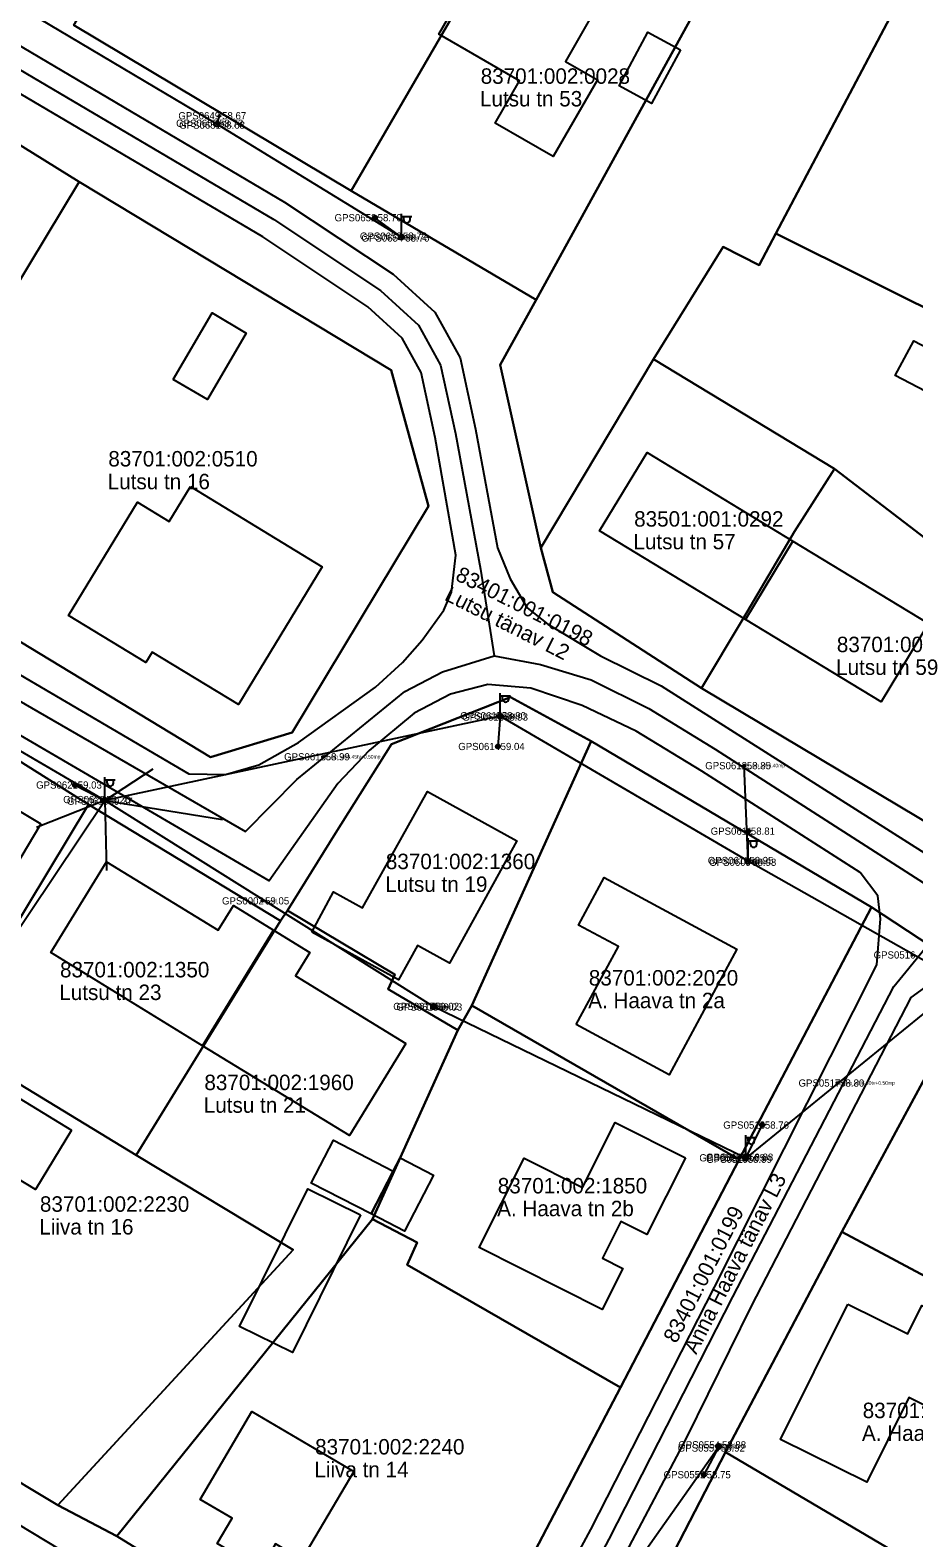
# Model space of a CAD drawing. Extents: x 580119 to 583377, y 6518915 to 6520820.
# Drawn here: x 581860.5 to 581946.3, y 6520226.6 to 6520373 of the extents above; entities that cross this region are included whole.
import ezdxf

# ---------------------------------------------------------------- set-up
doc = ezdxf.new("R2010")
doc.units = 0
for name, color, linetype in [('Hoone Elu- või ühiskondlik hoone', 7, 'Continuous'), ('Hoone Kõrval- või tootmishoone', 7, 'Continuous'), ('Hoone Vundament', 7, 'Continuous'), ('L_AADRESS', 7, 'Continuous'), ('MAAMUDEL', 7, 'Continuous'), ('MOOTKORG-EH2000', 7, 'Continuous'), ('MOOTMPUNKT', 7, 'Continuous'), ('MOOTNR', 7, 'Continuous'), ('MPOHULIIN', 7, 'Continuous'), ('PIIR', 7, 'Continuous'), ('POST', 7, 'Continuous'), ('Rippe kõrgus', 7, 'Continuous'), ('SIOHULIIN', 7, 'Continuous'), ('Tee Liiklusala', 7, 'Continuous'), ('Tee Tänav Püsikate', 7, 'Continuous'), ('TUNNUS', 7, 'Continuous')]:
    doc.layers.add(name, color=color, linetype=linetype)

msp = doc.modelspace()

# ---------------------------------------------------------------- linework, layer by layer
at = {"layer": 'Hoone Elu- või ühiskondlik hoone'}
for points in [[(581915.6, 6520368.18), (581911.32, 6520360.75), (581905.69, 6520363.98), (581908.05, 6520368.09), (581900.19, 6520372.62), (581905.37, 6520381.61), (581915.75, 6520375.63), (581912.49, 6520369.96)], [(581934.59, 6520323.38), (581929.97, 6520315.78), (581915.8, 6520324.38), (581920.42, 6520331.99)], [(581876.09, 6520328.69), (581888.89, 6520320.91), (581880.76, 6520307.52), (581872.37, 6520312.61), (581871.75, 6520311.61), (581864.25, 6520316.17), (581870.94, 6520327.17), (581874.03, 6520325.3)], [(581947.76, 6520315.39), (581943.15, 6520307.8), (581929.97, 6520315.78), (581934.59, 6520323.38)], [(581861.56, 6520295.95), (581856.33, 6520287.17), (581843.89, 6520294.57), (581845.86, 6520297.89), (581843.52, 6520299.28), (581848.15, 6520307.06), (581851.89, 6520304.84), (581850.52, 6520302.53)], [(581887.87, 6520285.43), (581889.97, 6520289.33), (581892.8, 6520287.77), (581899.11, 6520299.09), (581907.79, 6520294.29), (581901.23, 6520282.4), (581898.12, 6520284.11), (581896.29, 6520280.79)], [(581867.93, 6520292.26), (581878.78, 6520285.61), (581880.26, 6520288), (581884.15, 6520285.62), (581877.27, 6520274.39), (581862.52, 6520283.43)], [(581897.01, 6520274.62), (581891.52, 6520265.66), (581877.27, 6520274.39), (581884.15, 6520285.62), (581887.67, 6520283.46), (581886.28, 6520281.18)], [(581924.16, 6520263.52), (581920.4, 6520256.05), (581917.89, 6520257.31), (581916.1, 6520253.75), (581918.07, 6520252.76), (581916.07, 6520248.79), (581904.13, 6520254.79), (581908.49, 6520263.47), (581914.15, 6520260.63), (581917.33, 6520266.95)], [(581939.93, 6520249.3), (581945.73, 6520246.42), (581947.11, 6520249.18), (581953.35, 6520246.07), (581949.53, 6520238.4), (581945.84, 6520240.22), (581941.75, 6520232), (581933.39, 6520236.16)], [(581891.94, 6520233.04), (581886.91, 6520224.51), (581884.36, 6520226.01), (581882.91, 6520223.56), (581878.68, 6520226.06), (581880.13, 6520228.52), (581877.03, 6520230.34), (581882.05, 6520238.87)]]:
    msp.add_lwpolyline(points, close=True, dxfattribs=at)
at = {"layer": 'Hoone Kõrval- või tootmishoone'}
for points in [[(581923.66, 6520371.1), (581920.87, 6520365.9), (581917.71, 6520367.6), (581920.5, 6520372.8)], [(581874.4, 6520339.1), (581878.18, 6520345.55), (581881.51, 6520343.6), (581877.73, 6520337.15)], [(581952.19, 6520339.77), (581950.4, 6520336.39), (581944.53, 6520339.46), (581946.33, 6520342.85)], [(581864.55, 6520266.2), (581861.03, 6520260.42), (581855, 6520264.09), (581851.33, 6520258.06), (581844.97, 6520261.93), (581852.17, 6520273.74)], [(581895.77, 6520262.21), (581893.62, 6520258.06), (581887.81, 6520261.06), (581889.96, 6520265.21)], [(581893.62, 6520258.06), (581895.77, 6520262.21), (581896.44, 6520263.5), (581899.68, 6520261.83), (581896.87, 6520256.38)], [(581892.6, 6520257.96), (581885.98, 6520244.59), (581880.84, 6520247.12), (581887.47, 6520260.5)]]:
    msp.add_lwpolyline(points, close=True, dxfattribs=at)
at = {"layer": 'Hoone Vundament'}
msp.add_lwpolyline([(581913.55, 6520276.44), (581917.65, 6520284.03), (581913.78, 6520286.11), (581916.25, 6520290.72), (581929.14, 6520283.76), (581922.56, 6520271.57)], close=True, dxfattribs=at)
at = {"layer": 'MOOTMPUNKT'}
for centre in [(581878.9, 6520364.7), (581878.61, 6520363.97), (581878.77, 6520363.79), (581894, 6520354.8), (581896.46, 6520353.01), (581896.68, 6520352.83), (581906.06, 6520306.44), (581906.26, 6520306.32), (581905.94, 6520303.45), (581888.96, 6520302.45), (581929.85, 6520301.59), (581864.88, 6520299.71), (581867.65, 6520298.3), (581867.88, 6520298.14), (581930.24, 6520295.23), (581930.09, 6520292.38), (581930.37, 6520292.21), (581883.07, 6520288.46), (581946.2, 6520283.21), (581899.56, 6520278.21), (581899.87, 6520278.15), (581938.91, 6520270.77), (581931.6, 6520266.69), (581929.28, 6520263.51), (581930.07, 6520263.57), (581929.95, 6520263.37), (581927.44, 6520235.64), (581927.32, 6520235.33), (581925.95, 6520232.74)]:
    msp.add_circle(centre, 0.1, dxfattribs=at)
at = {"layer": 'MPOHULIIN'}
for p, q in [((581878.69, 6520363.88), (581878.9, 6520364.7)), ((581930.23, 6520292.3), (581929.85, 6520301.59)), ((581899.05, 6520195.29), (581927.38, 6520235.48))]:
    msp.add_line(p, q, dxfattribs=at)
for points in [[(581789.29, 6520345.21), (581806.35, 6520371.05), (581823.38, 6520396.51), (581838.05, 6520387.92), (581858.29, 6520376.01), (581878.69, 6520363.88), (581896.57, 6520352.92)], [(581867.76, 6520298.22), (581843.02, 6520312.69), (581821.56, 6520325.5), (581789.29, 6520345.21), (581785.52, 6520344.9)], [(581951.03, 6520280.57), (581930.23, 6520292.3), (581906.16, 6520306.38), (581867.76, 6520298.22)], [(581841.65, 6520259.23), (581850.68, 6520272.73), (581867.76, 6520298.22)], [(581951.03, 6520280.57), (581930.01, 6520263.47), (581928.35, 6520263.55)], [(581930.01, 6520263.47), (581899.71, 6520278.18)]]:
    msp.add_lwpolyline(points, dxfattribs=at)
at = {"layer": 'PIIR'}
for points in [[(581930.32, 6520416.52), (581957.49, 6520399.79), (581932.94, 6520353.26), (581931.31, 6520350.19), (581927.81, 6520351.97), (581921.06, 6520341.05), (581910.1, 6520322.74), (581906.17, 6520340.51), (581909.67, 6520346.83), (581927.24, 6520378.81), (581913.4, 6520387.09)], [(581883.02, 6520404.8), (581910, 6520388.99), (581891.69, 6520357.4), (581864.77, 6520373.51)], [(581957.49, 6520399.79), (581993.27, 6520378.24), (581969.51, 6520335.03), (581932.94, 6520353.26)], [(581910, 6520388.99), (581913.4, 6520387.09), (581927.24, 6520378.81), (581909.67, 6520346.83), (581891.69, 6520357.4)], [(581798.19, 6520351.98), (581821.38, 6520336.91), (581844, 6520323.04), (581878.03, 6520302.4), (581885.96, 6520304.82), (581899.19, 6520326.8), (581895.57, 6520340), (581865.29, 6520358.29), (581840.03, 6520373.94), (581817.44, 6520386.49)], [(581832.75, 6520354.9), (581829.56, 6520356.9), (581840.03, 6520373.94), (581865.29, 6520358.29), (581844, 6520323.04), (581821.38, 6520336.91)], [(581865.29, 6520358.29), (581895.57, 6520340), (581899.19, 6520326.8), (581885.96, 6520304.82), (581878.03, 6520302.4), (581844, 6520323.04)], [(581921.06, 6520341.05), (581927.81, 6520351.97), (581931.31, 6520350.19), (581932.94, 6520353.26), (581969.51, 6520335.03), (581969.36, 6520330.69), (581961, 6520313.29), (581938.63, 6520330.42)], [(581911.28, 6520318.44), (581910.1, 6520322.74), (581921.06, 6520341.05), (581938.63, 6520330.42), (581934.75, 6520324.34), (581929.71, 6520315.83), (581925.71, 6520309.1)], [(581938.63, 6520330.42), (581961, 6520313.29), (581950.66, 6520294.21), (581925.71, 6520309.1), (581929.71, 6520315.83), (581934.75, 6520324.34)], [(581849.2, 6520308.51), (581866.2, 6520297.82), (581852.4, 6520274.95), (581835.18, 6520285.22)], [(581895.94, 6520281.31), (581885.52, 6520287.54), (581890.17, 6520295.02), (581895.61, 6520303.69), (581907.15, 6520308.24), (581915, 6520303.97), (581903.41, 6520278.31), (581902.06, 6520275.9), (581895.28, 6520279.9)], [(581915, 6520303.97), (581942.22, 6520287.85), (581929.38, 6520263.33), (581903.41, 6520278.31)], [(581866.2, 6520297.82), (581884.83, 6520286.51), (581870.83, 6520263.78), (581852.4, 6520274.95)], [(581884.83, 6520286.51), (581885.52, 6520287.54), (581895.94, 6520281.31), (581895.28, 6520279.9), (581902.06, 6520275.9), (581893.75, 6520257.55), (581868.94, 6520226.76), (581863.22, 6520229.79), (581886.05, 6520254.56), (581870.83, 6520263.78)], [(581910.68, 6520201.36), (581900.21, 6520207.51), (581917.83, 6520241.2), (581929.38, 6520263.33), (581942.22, 6520287.85), (581953.73, 6520280.26), (581951.99, 6520279.75), (581939.33, 6520256.33), (581928.04, 6520234.91)], [(581951.99, 6520279.75), (581953.73, 6520280.26), (581978.64, 6520265.66), (581965.72, 6520242.24), (581939.33, 6520256.33)], [(581898.1, 6520255.28), (581893.75, 6520257.55), (581902.06, 6520275.9), (581903.41, 6520278.31), (581929.38, 6520263.33), (581917.83, 6520241.2), (581897.13, 6520253.13)], [(581841.97, 6520255.88), (581852.4, 6520274.95), (581870.83, 6520263.78), (581886.05, 6520254.56), (581863.22, 6520229.79), (581836.91, 6520245.57)], [(581893.75, 6520257.55), (581898.1, 6520255.28), (581897.13, 6520253.13), (581917.83, 6520241.2), (581900.21, 6520207.51), (581868.94, 6520226.76)], [(581939.33, 6520256.33), (581965.72, 6520242.24), (581963.58, 6520238.14), (581954.1, 6520219.54), (581928.04, 6520234.91)], [(581928.04, 6520234.91), (581954.1, 6520219.54), (581960.82, 6520215.52), (581942.75, 6520182.07), (581910.68, 6520201.36)]]:
    msp.add_lwpolyline(points, close=True, dxfattribs=at)
for points in [[(581953.73, 6520280.26), (581942.22, 6520287.85), (581915, 6520303.97), (581907.15, 6520308.24), (581895.61, 6520303.69), (581890.17, 6520295.02), (581885.52, 6520287.54), (581884.83, 6520286.51), (581866.2, 6520297.82), (581849.2, 6520308.51), (581832.08, 6520318.73), (581821.48, 6520324.8), (581804.32, 6520335.14), (581786.62, 6520345.32), (581785.35, 6520349.14), (581801.36, 6520378.94)], [(581864.77, 6520373.51), (581891.69, 6520357.4), (581909.67, 6520346.83), (581906.17, 6520340.51), (581910.1, 6520322.74), (581911.28, 6520318.44), (581925.71, 6520309.1), (581950.66, 6520294.21)], [(581641.44, 6520358.2), (581663.75, 6520346.68), (581696.78, 6520330.58), (581710.47, 6520322.41), (581741.73, 6520303.41), (581773.45, 6520284.3), (581791.76, 6520272.95), (581801.15, 6520267.32), (581804.72, 6520265.17), (581827.76, 6520250.96), (581836.91, 6520245.57), (581863.22, 6520229.79), (581868.94, 6520226.76), (581900.21, 6520207.51)]]:
    msp.add_lwpolyline(points, dxfattribs=at)
at = {"layer": 'POST'}
for p, q in [((581896.57, 6520353.17), (581896.57, 6520355.17)), ((581896.57, 6520354.92), (581897.57, 6520354.92)), ((581896.8, 6520354.6), (581896.8, 6520354.92)), ((581897.41, 6520354.6), (581897.41, 6520354.92)), ((581896.57, 6520352.92), (581896.57, 6520352.92)), ((581906.16, 6520306.63), (581906.16, 6520308.63)), ((581906.16, 6520308.38), (581907.16, 6520308.38)), ((581906.39, 6520308.06), (581906.39, 6520308.38)), ((581907, 6520308.06), (581907, 6520308.38)), ((581906.16, 6520306.38), (581906.16, 6520306.38)), ((581867.76, 6520298.47), (581867.76, 6520300.47)), ((581867.76, 6520300.22), (581868.76, 6520300.22)), ((581867.99, 6520299.9), (581867.99, 6520300.22)), ((581868.6, 6520299.9), (581868.6, 6520300.22)), ((581867.76, 6520298.22), (581867.76, 6520298.22)), ((581930.23, 6520292.55), (581930.23, 6520294.55)), ((581930.23, 6520294.3), (581931.23, 6520294.3)), ((581930.46, 6520293.97), (581930.46, 6520294.3)), ((581931.07, 6520293.97), (581931.07, 6520294.3)), ((581930.23, 6520292.3), (581930.23, 6520292.3)), ((581930.01, 6520263.72), (581930.01, 6520265.72)), ((581930.01, 6520265.47), (581931.01, 6520265.47)), ((581930.23, 6520265.15), (581930.23, 6520265.47)), ((581930.84, 6520265.15), (581930.84, 6520265.47)), ((581930.01, 6520263.47), (581930.01, 6520263.47))]:
    msp.add_line(p, q, dxfattribs=at)
for points in [[(581896.57, 6520352.92), (581894, 6520354.8)], [(581906.16, 6520306.38), (581905.94, 6520303.45)], [(581864.88, 6520299.71), (581867.76, 6520298.22)], [(581930.01, 6520263.47), (581931.6, 6520266.69)], [(581927.38, 6520235.48), (581925.95, 6520232.74)]]:
    msp.add_lwpolyline(points, dxfattribs=at)
for centre, radius in [((581878.69, 6520363.88), 0.25), ((581894, 6520354.8), 0.2), ((581896.57, 6520352.92), 0.25), ((581906.16, 6520306.38), 0.25), ((581905.94, 6520303.45), 0.2), ((581864.88, 6520299.71), 0.2), ((581867.76, 6520298.22), 0.25), ((581930.24, 6520295.23), 0.2), ((581930.23, 6520292.3), 0.25), ((581899.71, 6520278.18), 0.25), ((581899.71, 6520278.18), 0.0234), ((581931.6, 6520266.69), 0.2), ((581930.01, 6520263.47), 0.25), ((581927.38, 6520235.48), 0.25), ((581925.95, 6520232.74), 0.2)]:
    msp.add_circle(centre, radius, dxfattribs=at)
for centre in [(581897.1, 6520354.6), (581906.69, 6520308.06), (581868.3, 6520299.9), (581930.77, 6520293.97), (581930.54, 6520265.15)]:
    msp.add_arc(centre, 0.306, 180, 0, dxfattribs=at)
at = {"layer": 'SIOHULIIN'}
for q in [(581872.48, 6520301.27), (581861.13, 6520295.58), (581867.95, 6520291.41)]:
    msp.add_line((581867.76, 6520298.22), q, dxfattribs=at)
for points in [[(581867.76, 6520298.22), (581879.19, 6520296.36)], [(581899.71, 6520278.18), (581867.76, 6520298.22)]]:
    msp.add_lwpolyline(points, dxfattribs=at)
at = {"layer": 'Tee Liiklusala'}
for points in [[(581843.85, 6520381.18), (581859.87, 6520371.29), (581885.23, 6520356.32), (581895.77, 6520349.31), (581899.82, 6520345.62), (581902.26, 6520341.18), (581903.77, 6520334.25), (581905.9, 6520322.74), (581907.13, 6520319.74), (581908.78, 6520316.91), (581910.79, 6520315.32), (581915.9, 6520312.25), (581921.78, 6520309.33), (581947.38, 6520293.09)], [(581845.58, 6520318.61), (581875.93, 6520300.79), (581879.5, 6520300.73), (581882.72, 6520301.66), (581886.58, 6520303.83), (581894.07, 6520309.22), (581896.69, 6520311.61), (581898.59, 6520313.79), (581900.69, 6520316.7), (581901.45, 6520318.45), (581901.87, 6520322.02), (581899.85, 6520333.46), (581898.48, 6520339.76), (581896.64, 6520343.11), (581893.3, 6520346.15), (581883.11, 6520352.93), (581857.8, 6520367.86)], [(581905.87, 6520210.56), (581914.97, 6520227.4), (581926.96, 6520250.94), (581942.73, 6520282.24), (581943.1, 6520286.73), (581942.84, 6520288.94), (581941.11, 6520291.22), (581925.73, 6520301.07), (581919.37, 6520304.95), (581914.13, 6520307.42), (581909.15, 6520309.1), (581904.96, 6520309.47), (581901.34, 6520308.53), (581897.81, 6520306.68), (581893.45, 6520303.06), (581890.4, 6520299.87), (581883.73, 6520290.39), (581831.98, 6520320.65)], [(581948.5, 6520280.84), (581946.04, 6520279.06), (581930.52, 6520249.11), (581924.23, 6520236.3), (581909.68, 6520208.73), (581908.39, 6520205.89), (581907.88, 6520203.6), (581907.85, 6520201.97), (581908.78, 6520199.57), (581909.94, 6520197.81), (581951.81, 6520172.47)], [(581822.23, 6520250.37), (581872.96, 6520219.7)]]:
    msp.add_lwpolyline(points, dxfattribs=at)
at = {"layer": 'Tee Tänav Püsikate'}
for points in [[(581829.4, 6520325.26), (581818.11, 6520332.41), (581802.94, 6520342.03), (581797.05, 6520345.98), (581794.58, 6520349.99), (581793.88, 6520354.52), (581794.87, 6520358.14), (581805.2, 6520378.63), (581809.48, 6520385.25), (581812.61, 6520388.5), (581816.17, 6520390.21), (581820.37, 6520391.25), (581824.11, 6520390.41), (581827.72, 6520388.92), (581832.69, 6520386.31), (581842.76, 6520379.5), (581858.83, 6520369.58), (581884.17, 6520354.62), (581894.53, 6520347.73), (581898.23, 6520344.36), (581900.37, 6520340.47), (581901.81, 6520333.85), (581904.24, 6520320.68), (581905.59, 6520312.25)], [(581829.4, 6520325.26), (581847.74, 6520314.64), (581881.43, 6520295.18), (581886.42, 6520300.23), (581896.89, 6520308.78), (581900.56, 6520310.7), (581905.59, 6520312.25)], [(581905.59, 6520312.25), (581910.07, 6520311.41), (581914.98, 6520309.92), (581920.58, 6520307.14), (581927.05, 6520303.19), (581949.43, 6520288.83), (581950.77, 6520287.95)], [(581904.38, 6520197.95), (581905.85, 6520205.86), (581916.75, 6520226.48), (581928.74, 6520250.02), (581944.37, 6520280.16), (581950.77, 6520287.95)]]:
    msp.add_lwpolyline(points, dxfattribs=at)

# ---------------------------------------------------------------- texts
at = {"layer": 'L_AADRESS'}
for s, p in [('Lutsu tn 53', (581904.2, 6520365.6)), ('Lutsu tn 16', (581868.05, 6520328.43)), ('Lutsu tn 57', (581919.1, 6520322.6)), ('Lutsu tn 59', (581938.78, 6520310.4)), ('Lutsu tn 19', (581895, 6520289.33)), ('Lutsu tn 23', (581863.35, 6520278.83)), ('A. Haava tn 2a', (581914.71, 6520278.04)), ('Lutsu tn 21', (581877.38, 6520267.88)), ('A. Haava tn 2b', (581905.87, 6520257.84)), ('Liiva tn 16', (581861.41, 6520256.06)), ('A. Haava tn 3', (581941.29, 6520236.02)), ('Liiva tn 14', (581888.12, 6520232.49))]:
    msp.add_text(s, height=1.5, dxfattribs=at).set_placement(p)
for s, rotation, p in [('Lutsu tänav L2', 333.1829, (581900.65, 6520317.72)), ('Anna Haava tänav L3', 62.8457, (581925.19, 6520244.34))]:
    msp.add_text(s, height=1.5, rotation=rotation, dxfattribs=at).set_placement(p)
at = {"layer": 'MAAMUDEL'}
for s, p in [(' kaabel', (581896.46, 6520352.84)), (' kaabel', (581896.68, 6520352.66)), (' kaabel', (581906.06, 6520306.26)), (' kaabel', (581906.26, 6520306.14)), (' kilp', (581930.09, 6520292.21)), (' kaabel', (581930.09, 6520292.21)), (' kilp', (581930.37, 6520292.03)), (' kaabel', (581930.37, 6520292.03)), (' si_ohl', (581883.07, 6520288.29)), (' kaabel', (581899.56, 6520278.04)), (' kaabel', (581899.87, 6520277.98)), (' kaabel', (581927.44, 6520235.46)), (' kaabel', (581927.32, 6520235.15))]:
    msp.add_text(s, height=0.35, dxfattribs=at).set_placement(p)
at = {"layer": 'MOOTKORG-EH2000'}
for s, p in [(' 58.67', (581878.9, 6520364.35)), (' 58.73', (581878.61, 6520363.62)), (' 58.68', (581878.77, 6520363.44)), (' 58.70', (581894, 6520354.45)), (' 58.72', (581896.46, 6520352.66)), (' 58.76', (581896.68, 6520352.48)), (' 58.90', (581906.06, 6520306.09)), (' 58.93', (581906.26, 6520305.96)), (' 59.04', (581905.94, 6520303.1)), (' 58.99', (581888.96, 6520302.1)), (' 58.85', (581929.85, 6520301.24)), (' 59.03', (581864.88, 6520299.36)), (' 59.20', (581867.65, 6520297.95)), (' 59.37', (581867.88, 6520297.79)), (' 58.81', (581930.24, 6520294.88)), (' 58.95', (581930.09, 6520292.03)), (' 58.93', (581930.37, 6520291.86)), (' 59.05', (581883.07, 6520288.11)), (' 59.02', (581899.56, 6520277.86)), (' 59.03', (581899.87, 6520277.8)), (' 58.80', (581938.91, 6520270.42)), (' 58.76', (581931.6, 6520266.34)), (' 59.05', (581929.28, 6520263.16)), (' 58.99', (581929.95, 6520263.02)), (' 58.88', (581930.07, 6520263.22)), (' 58.92', (581927.32, 6520234.98)), (' 58.88', (581927.44, 6520235.29)), (' 58.75', (581925.95, 6520232.39))]:
    msp.add_text(s, height=0.7, dxfattribs=at).set_placement(p)
at = {"layer": 'MOOTNR'}
for s, p in [('GPS0649 ', (581874.91, 6520364.35)), ('GPS0650 ', (581874.69, 6520363.62)), ('GPS0651 ', (581874.99, 6520363.44)), ('GPS0652 ', (581890.08, 6520354.45)), ('GPS0653 ', (581892.54, 6520352.66)), ('GPS0654 ', (581892.69, 6520352.48)), ('GPS0615 ', (581902.28, 6520306.09)), ('GPS0616 ', (581902.48, 6520305.96)), ('GPS0614 ', (581902.09, 6520303.1)), ('GPS0613 ', (581885.18, 6520302.1)), ('GPS0612 ', (581926.07, 6520301.24)), ('GPS0621 ', (581861.1, 6520299.36)), ('GPS0620 ', (581863.73, 6520297.95)), ('GPS0619 ', (581864.1, 6520297.79)), ('GPS0611 ', (581926.6, 6520294.88)), ('GPS0610 ', (581926.32, 6520292.03)), ('GPS0609 ', (581926.45, 6520291.86)), ('GPS0002 ', (581879.15, 6520288.11)), ('GPS0516 ', (581942.42, 6520282.86)), ('GPS0617 ', (581895.78, 6520277.86)), ('GPS0618 ', (581896.09, 6520277.8)), ('GPS0517 ', (581935.13, 6520270.42)), ('GPS0518 ', (581927.82, 6520266.34)), ('GPS0521 ', (581925.5, 6520263.16)), ('GPS0520 ', (581926.15, 6520263.22)), ('GPS0519 ', (581926.17, 6520263.02)), ('GPS0553 ', (581923.4, 6520234.98)), ('GPS0554 ', (581923.45, 6520235.29)), ('GPS0552 ', (581922.03, 6520232.39))]:
    msp.add_text(s, height=0.7, dxfattribs=at).set_placement(p)
at = {"layer": 'Rippe kõrgus'}
for s, p in [(' el_mp_ohl5.45tv+0.50mp', (581888.96, 6520302.28)), (' el_mp_ohl5.40mp', (581929.85, 6520301.42)), (' el_mp_ohl6.90tv+0.50mp', (581938.91, 6520270.6))]:
    msp.add_text(s, height=0.35, dxfattribs=at).set_placement(p)
at = {"layer": 'TUNNUS'}
for s, p in [('83701:002:0028', (581904.27, 6520367.8)), ('83701:002:0510', (581868.11, 6520330.64)), ('83501:001:0292', (581919.17, 6520324.8)), ('83701:002:1810', (581938.85, 6520312.61)), ('83701:002:1360', (581895.06, 6520291.54)), ('83701:002:1350', (581863.42, 6520281.03)), ('83701:002:2020', (581914.77, 6520280.24)), ('83701:002:1960', (581877.44, 6520270.08)), ('83701:002:1850', (581905.93, 6520260.05)), ('83701:002:2230', (581861.47, 6520258.27)), ('83701:002:1800', (581941.36, 6520238.23)), ('83701:002:2240', (581888.19, 6520234.7))]:
    msp.add_text(s, height=1.5, dxfattribs=at).set_placement(p)
for s, rotation, p in [('83401:001:0198', 333.1829, (581901.71, 6520319.66)), ('83401:001:0199', 62.8457, (581923.26, 6520245.41))]:
    msp.add_text(s, height=1.5, rotation=rotation, dxfattribs=at).set_placement(p)

doc.saveas('drawing.dxf')
